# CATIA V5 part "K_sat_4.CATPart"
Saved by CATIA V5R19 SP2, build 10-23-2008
Part number: sat 4
Source: Unknown
Publications: "Plan.14"
Material "Aucun"
Bounding box of the stored display mesh (mm): x -63.515 to 63.515, y -63.573 to 63.573, z -18.921 to 41.193
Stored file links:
  G:\Khaled_CFAO_2011\ST2M\ST2M_GR1\mponsin\Khaled\CAD_ThinkMOTION\K_sat_4.CATPart
  C:\Program Files\Dassault Systemes\B20\win_b64\startup\materials\French\Catalog.CATMaterial
  C:\Users\Socar\Documents\thinkmotion\Final\Diff2.CATProduct
  G:\Khaled_CFAO_2011\ST2M\ST2M_GR1\mponsin\Khaled\CAD_ThinkMOTION\K_mponsin.CATProduct
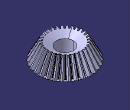
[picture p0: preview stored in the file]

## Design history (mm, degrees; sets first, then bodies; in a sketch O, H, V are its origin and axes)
Parameters
  Z1 = 30 {= External.Zs}
  delta = 26.5651 deg {= atan(External.Zs /External.Zp )}
  a = 20 deg
  m = 4 mm {= External.Module}
  ld = 44.7214 mm {= m *Z1 /(3*2*sin(delta ))}
  dZ = 0 mm
  p = 12.5664 mm {= m * PI}
  rp = 60 mm {= m * Z1 / 2}
  rc = 67.082 mm {= rp / cos( delta )}
  rb = 63.0365 mm {= rc * cos( a )}
  lc = 150 mm {= rc / sin( delta )}
  ha = 4 mm {= m}
  hf = 5 mm {= 1.25 * m}
  rr = 1.4608 mm {= Set2.Offset * 0.7763}
  tc = -0.7576 deg
  ratio = 0.666667 {= 1 - ld / lc / cos( delta )}
External parameters (linked from other documents)
  External.Zp = 60
  External.Zs = 30
  External.Module = 4 mm
Intersect1 "coin de fond": ToIntersect1 Project1, ToIntersect2 Circle4
Point1: type OnCurve, Support Line7, Length 5 {= hf}
Set1 "cones primitifs"
  Line1 "Axe Z": stored without definition
  Point2 "sommet arriere": (0, 0, -30 {= dZ - rp * tan( delta )})
  Point3 "sommet avant": type OnCurve, Support Line1, RefPoint Point2, Length 150 {= lc}
  Line2: type PtPt, FirstPoint Point2, SecondPoint Point3
  Line3: type Angle, RefPoint Point3, Curve Line2, Support zx-plane, Start 0, End 134.1641 {= lc * cos( delta )}, Angle -26.5651 {= -delta}
  Line4: type PtPt, FirstPoint Point2, SecondPoint vertex of Line3, Start 0
  Plane1 "plan_primitif": type OffsetPt, RefPlane xy-plane, RefPoint vertex of Line3
  Intersect2: ToIntersect1 Plane1, ToIntersect2 Line2
  Circle1 "arc primitif": type CtrPt, Start 0, End 30, Center Intersect2, Support Plane1, RefPoint vertex of Line3
  Circle2 "cercle primitif": type CtrRad, Start 0, End 90, Center Intersect2, Support Plane1, Radius 60 {= rp}, FirstDirection (1, 0, 0)
Set2 "profil dent"
  Point4 "point 0": type OnPlane, Support Plane2, RefPoint Point2, H 63.0365, V 0, Direction (1, 0, 0)
  Point5 "point 1": type OnPlane, Support Plane2, RefPoint Point2, H 66.0709, V 0.6451, Direction (1, 0, 0)
  Point6 "point 2": type OnPlane, Support Plane2, RefPoint Point2, H 74.278, V 5.0092, Direction (1, 0, 0)
  Point7 "point 3": type OnPlane, Support Plane2, RefPoint Point2, H 85.116, V 16.077, Direction (1, 0, 0)
  Curve1: Elements (Point4; Point5; Point6; Point7)
  Extrapol1: ToExtrapol Point4, Support Curve1, Length 8 {= 2 * m}
  Plane2: type Normal, Curve Line3, RefPoint Point2
  Symmetry1: Reference vertex of Line3, ToTransfor Point2
  Line5: type PtPt, FirstPoint Point2, SecondPoint Symmetry1
  Point8: type OnCurve, Support Line5, Ratio 0.25
  Line6: type PtPt, FirstPoint Point8, SecondPoint vertex of Line5
  Revol1: Element1 Line6, Line Line1, Angle1 0
  Project1: ToProject Extrapol1, Support Revol1, Direction Line3
  Intersect3: ToIntersect1 Circle1, ToIntersect2 Project1
  Plane3 "plan contact": type 1Line1Pt, RefPoint Intersect3, Line Line1
  Circle3 "cercle primitif": type CtrPt, Start 3 {= 90deg / Z1}, End -3 {= -90deg / Z1}, Center Intersect2, Support Plane1, RefPoint Intersect3
  Plane4 "plan median": type 1Line1Pt, RefPoint vertex of Circle3, Line Line1
  Line7 "droite debut": type PtPt, FirstPoint vertex of Circle3, SecondPoint Point2
  Plane5 "plan_fond": type OffsetPt, RefPlane xy-plane, RefPoint Point1
  Intersect4: ToIntersect1 Plane5, ToIntersect2 Line2
  Circle4 "cercle de fond": type CtrPt, Start 0, End 30, Center Intersect4, Support Plane5, RefPoint Point1
  Point9: type OnCurve, Support Line7, Length -4 {= -ha}
  Plane6 "plan_tete": type OffsetPt, RefPlane xy-plane, RefPoint Point9
  Intersect5: ToIntersect1 Plane6, ToIntersect2 Line2
  Circle5 "cercle de tete": type CtrPt, Start 0, End 30, Center Intersect5, Support Plane6, RefPoint Point9
  Split1 "segment flanc": ToCut Project1, Cutting Plane5
  Split2 "segment fond": ToCut Circle4, Cutting Project1
  Corner1: Element1 Split1, Element2 Split2, Support Revol1, Radius 1.4301 {= Set2.Offset * 0.76}
  Symmetry2: Reference Plane4, ToTransfor Corner1
  Trim1: Element1 Corner1, Element2 Circle5
  Trim2: Element1 Trim1, Element2 Symmetry2
Set3 "surface dent"
  Point10 "fin denture": type OnCurve, Support Line3, Length 44.7214 {= ld}
  Scaling1: Reference Point3, Ratio 0.666667 {= ratio}, ToTransfor Trim2
  Line8: type PtPt, FirstPoint vertex of Scaling1, SecondPoint Point1
  Line9: type PtPt, FirstPoint vertex of Scaling1, SecondPoint vertex of Trim2
  Loft1: Sections (Trim2; Scaling1), Guides (Line8; Line9)
  CircPattern1: of Loft1, instances 30 {= Z1}, angular step 12 {= 360.0*1 deg/CircPattern1.AngularNumber}, axis from Line2
Set4 "flanc dent"
  CircPattern2: of Trim2, instances 30 {= Z1}, angular step 12 {= 360.0*1 deg/CircPattern2.AngularNumber}, axis from Line2
  Join1: Elements (CircPattern2; Trim2)
  Split3: ToCut Revol1, Cutting Join1
  Scaling2: Reference Point3, Ratio 0.666667 {= ratio}, ToTransfor Split3
  Fill1: Boundary edge of Scaling2
  Join2: Elements (Split3; CircPattern1; Scaling2; Fill1; Loft1)
  Plane7: type 1Curve, Element1 edge [face of Shaft1 from Sketch1.L2 | face of Shaft2]
Body1 (main body)
  Sketch1 on zx-plane, origin (0, 0, 0), H (-1, 0, 0), V (0, 0, 1)
    point P1 (-30, -15)
    line L1 (0, 0) -> (0, -18.9213)
    line L2 (0, -18.9213) -> (-30, -18.9213)
    line L3 (-30, -18.9213) -> (-30, -15)
    reference projected point E1 (-30, -15) from Point8
    line L4 (-30, -15) -> (-60, 0)
    point P5 (-60, 0)
    line L5 (0, 0) -> (-60, 0)
    reference projected point E2 (-60, 0) from vertex of Line4
    horizontal: L2 H, L5 H
    vertical: L1 V, L3 V
    coincidence: P1 E1, L1 V, P5 E2
  Shaft1: profile Sketch1, axis Line1, angle 360
  CloseSurface1: CloseElement Join2
  Sketch2 on xy-plane, origin (0, 0, 0), H (1, 0, 0), V (0, 1, 0)
    circle A1 centre (0, 0) radius 20
    radius A1 = 20
  Pocket1: profile Sketch2, direction (0, 0, 1), through (limit type 6), opposite side through (limit type 6)
  Body2
    Sketch3 on zx-plane, origin (0, 0, 0), H (-1, 0, 0), V (0, 0, 1)
      line L1 (0, -30) -> (333.9525, -10)
      point P1 (0, -30)
      point P2 (333.9525, -10)
      line L2 (333.9525, -10) -> (30, -10)
      point P3 (333.9525, -10)
      line L3 (30, -10) -> (30, -20)
      line L4 (30, -20) -> (0, -20)
      point P6 (0, -20)
      line L5 (0, -20) -> (0, -30)
      reference projected point E1 (0, -30) from Point2
      length L3 = 10
      length L4 = 30
      distance L2 H = 10
      length L2 = 303.9525
      coincidence: P1 V, P3 L1, P6 V, P2 P3, P1 E1
      horizontal: L2 H, L4 H
      vertical: L3 V, L5 V
    Shaft2: profile Sketch3, axis Sketch3.L5, angle 360
  Remove1: tool Body2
